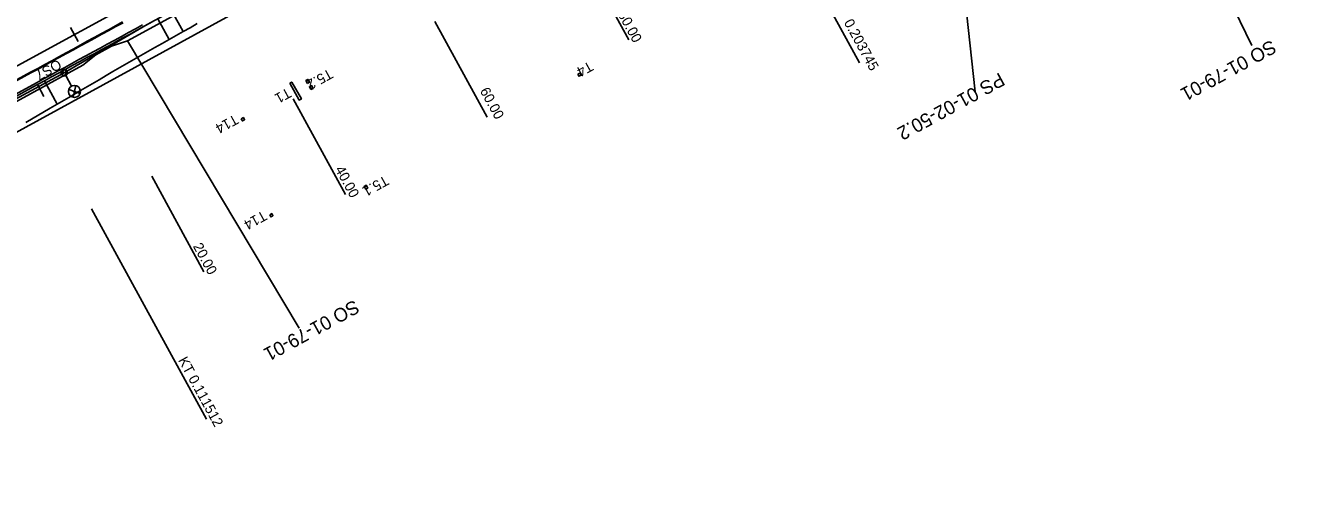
# Model space of a CAD drawing. Extents: x -783978 to -783565, y -1064821 to -1064596.
# Drawn here: x -783865.7 to -783706.3, y -1064790 to -1064732.7 of the extents above; entities that cross this region are included whole.
import ezdxf

# ---------------------------------------------------------------- set-up
doc = ezdxf.new("R2010")
doc.units = 0
for name, color, linetype in [('_PS_SO_číslo', 7, 'Continuous'), ('PS 01_01_10', 7, 'Continuous'), ('PS 01_02_501', 7, 'Continuous'), ('PS 01_02_502', 7, 'Continuous'), ('SO 01_50_01', 7, 'Continuous'), ('SO 01_77_01', 7, 'Continuous'), ('SO 01_79_02', 7, 'Continuous'), ('SO 01_86_02', 7, 'Continuous'), ('SO 01_86_03', 7, 'Continuous')]:
    doc.layers.add(name, color=color, linetype=linetype)

msp = doc.modelspace()

# ---------------------------------------------------------------- linework, layer by layer
at = {"layer": '_PS_SO_číslo'}
for p, q in [((-783752.54, -1064700.01), (-783748.07, -1064740.95)), ((-783725.4, -1064711.21), (-783713.77, -1064735.19)), ((-783853.11, -1064734.61), (-783831.84, -1064770.24))]:
    msp.add_line(p, q, dxfattribs=at)
at = {"layer": 'PS 01_01_10'}
msp.add_lwpolyline([(-783718.94, -1064658.94), (-783725.96, -1064662.69), (-783732.35, -1064665.91), (-783735.21, -1064660.7), (-783789.36, -1064690.35), (-783783.83, -1064700.44), (-783871.44, -1064748.42), (-783875.86, -1064749.83)], dxfattribs=at)
at = {"layer": 'PS 01_02_501'}
msp.add_lwpolyline([(-783952.31, -1064789.97), (-783925.03, -1064771.23), (-783922.86, -1064767.94), (-783921.13, -1064767.23), (-783922.34, -1064769.06), (-783920.82, -1064771.04), (-783917.67, -1064770.42), (-783911.05, -1064766.47), (-783887.43, -1064753.52), (-783871.44, -1064748.42), (-783783.83, -1064700.44), (-783789.36, -1064690.35), (-783735.23, -1064660.71), (-783727.19, -1064659.07), (-783724.3, -1064658.48), (-783715.52, -1064653.99), (-783697.39, -1064644.15), (-783676.27, -1064633.51), (-783655.14, -1064621.89)], dxfattribs=at)
at = {"layer": 'PS 01_02_502'}
msp.add_lwpolyline([(-783952.31, -1064789.97), (-783925.03, -1064771.23), (-783922.86, -1064767.94), (-783921.13, -1064767.23), (-783922.34, -1064769.06), (-783920.82, -1064771.04), (-783917.67, -1064770.42), (-783911.05, -1064766.47), (-783887.43, -1064753.52), (-783871.44, -1064748.42), (-783783.83, -1064700.44), (-783789.36, -1064690.35), (-783735.23, -1064660.71), (-783727.19, -1064659.07), (-783724.3, -1064658.48), (-783715.52, -1064653.99), (-783697.39, -1064644.15), (-783676.27, -1064633.51), (-783655.14, -1064621.89)], dxfattribs=at)
at = {"layer": 'SO 01_50_01'}
for p, q in [((-783867.16, -1064737.91), (-783786.21, -1064693.71)), ((-783776.63, -1064711.26), (-783762.39, -1064737.33)), ((-783797.47, -1064722.64), (-783791, -1064734.49)), ((-783847.62, -1064730.94), (-783846.24, -1064733.48)), ((-783854.61, -1064732.76), (-783853.73, -1064732.28)), ((-783854.61, -1064732.76), (-783853.73, -1064732.28)), ((-783854.56, -1064732.85), (-783853.68, -1064732.37)), ((-783851.13, -1064732.86), (-783850.26, -1064732.38)), ((-783851.13, -1064732.86), (-783850.26, -1064732.38)), ((-783851.13, -1064732.86), (-783850.26, -1064732.38)), ((-783849.38, -1064731.9), (-783847.98, -1064734.46)), ((-783845.37, -1064732.99), (-783844.5, -1064732.49)), ((-783815.02, -1064732.23), (-783808.55, -1064744.07)), ((-783859.23, -1064734.72), (-783860.19, -1064732.96)), ((-783858.12, -1064734.68), (-783857.24, -1064734.2)), ((-783858.12, -1064734.68), (-783857.24, -1064734.2)), ((-783857.24, -1064734.2), (-783856.36, -1064733.72)), ((-783857.24, -1064734.2), (-783856.36, -1064733.72)), ((-783857.19, -1064734.29), (-783856.31, -1064733.81)), ((-783856.36, -1064733.72), (-783855.48, -1064733.24)), ((-783856.36, -1064733.72), (-783855.48, -1064733.24)), ((-783856.31, -1064733.81), (-783855.44, -1064733.33)), ((-783855.48, -1064733.24), (-783854.61, -1064732.76)), ((-783855.48, -1064733.24), (-783854.61, -1064732.76)), ((-783855.44, -1064733.33), (-783854.56, -1064732.85)), ((-783854.77, -1064734.56), (-783853.89, -1064734.08)), ((-783853.89, -1064734.08), (-783853.01, -1064733.6)), ((-783853.77, -1064734.3), (-783852.89, -1064733.82)), ((-783853.77, -1064734.3), (-783852.89, -1064733.82)), ((-783853.77, -1064734.3), (-783852.89, -1064733.82)), ((-783853.01, -1064733.6), (-783852.13, -1064733.12)), ((-783852.89, -1064733.82), (-783852.01, -1064733.34)), ((-783852.89, -1064733.82), (-783852.01, -1064733.34)), ((-783852.89, -1064733.82), (-783852.01, -1064733.34)), ((-783852.13, -1064733.12), (-783851.25, -1064732.64)), ((-783852.01, -1064733.34), (-783851.13, -1064732.86)), ((-783852.01, -1064733.34), (-783851.13, -1064732.86)), ((-783852.01, -1064733.34), (-783851.13, -1064732.86)), ((-783847.98, -1064734.46), (-783847.11, -1064733.97)), ((-783847.11, -1064733.97), (-783846.24, -1064733.48)), ((-783846.24, -1064733.48), (-783845.37, -1064732.99)), ((-783860.75, -1064736.12), (-783859.87, -1064735.64)), ((-783860.75, -1064736.12), (-783859.87, -1064735.64)), ((-783860.7, -1064736.21), (-783859.82, -1064735.73)), ((-783859.87, -1064735.64), (-783858.99, -1064735.16)), ((-783859.87, -1064735.64), (-783858.99, -1064735.16)), ((-783859.82, -1064735.73), (-783858.95, -1064735.25)), ((-783858.99, -1064735.16), (-783858.12, -1064734.68)), ((-783858.99, -1064735.16), (-783858.12, -1064734.68)), ((-783858.95, -1064735.25), (-783858.07, -1064734.77)), ((-783858.07, -1064734.77), (-783857.19, -1064734.29)), ((-783857.4, -1064736), (-783856.52, -1064735.52)), ((-783857.28, -1064736.22), (-783856.4, -1064735.74)), ((-783857.28, -1064736.22), (-783856.4, -1064735.74)), ((-783857.28, -1064736.22), (-783856.4, -1064735.74)), ((-783856.52, -1064735.52), (-783855.64, -1064735.04)), ((-783856.4, -1064735.74), (-783855.52, -1064735.26)), ((-783856.4, -1064735.74), (-783855.52, -1064735.26)), ((-783856.4, -1064735.74), (-783855.52, -1064735.26)), ((-783855.64, -1064735.04), (-783854.77, -1064734.56)), ((-783855.52, -1064735.26), (-783854.65, -1064734.78)), ((-783855.52, -1064735.26), (-783854.65, -1064734.78)), ((-783855.52, -1064735.26), (-783854.65, -1064734.78)), ((-783854.65, -1064734.78), (-783853.77, -1064734.3)), ((-783854.65, -1064734.78), (-783853.77, -1064734.3)), ((-783854.65, -1064734.78), (-783853.77, -1064734.3)), ((-783850.59, -1064735.94), (-783849.72, -1064735.45)), ((-783849.72, -1064735.45), (-783848.85, -1064734.96)), ((-783848.85, -1064734.96), (-783847.98, -1064734.46)), ((-783863.38, -1064737.56), (-783862.51, -1064737.08)), ((-783863.38, -1064737.56), (-783862.51, -1064737.08)), ((-783863.34, -1064737.64), (-783862.46, -1064737.16)), ((-783862.51, -1064737.08), (-783861.63, -1064736.6)), ((-783862.51, -1064737.08), (-783861.63, -1064736.6)), ((-783862.46, -1064737.16), (-783861.58, -1064736.68)), ((-783861.63, -1064736.6), (-783860.75, -1064736.12)), ((-783861.63, -1064736.6), (-783860.75, -1064736.12)), ((-783861.58, -1064736.68), (-783860.7, -1064736.21)), ((-783860.03, -1064737.43), (-783859.15, -1064736.95)), ((-783859.91, -1064737.65), (-783859.03, -1064737.17)), ((-783859.91, -1064737.65), (-783859.03, -1064737.17)), ((-783859.91, -1064737.65), (-783859.03, -1064737.17)), ((-783859.15, -1064736.95), (-783858.28, -1064736.48)), ((-783859.03, -1064737.17), (-783858.16, -1064736.69)), ((-783859.03, -1064737.17), (-783858.16, -1064736.69)), ((-783859.03, -1064737.17), (-783858.16, -1064736.69)), ((-783858.28, -1064736.48), (-783857.4, -1064736)), ((-783858.16, -1064736.69), (-783857.28, -1064736.22)), ((-783858.16, -1064736.69), (-783857.28, -1064736.22)), ((-783858.16, -1064736.69), (-783857.28, -1064736.22)), ((-783854.07, -1064737.92), (-783853.2, -1064737.42)), ((-783853.2, -1064737.42), (-783852.33, -1064736.93)), ((-783852.33, -1064736.93), (-783851.46, -1064736.43)), ((-783851.46, -1064736.43), (-783850.59, -1064735.94)), ((-783868.9, -1064740.57), (-783865.14, -1064738.51)), ((-783868.88, -1064740.67), (-783865.09, -1064738.6)), ((-783866.02, -1064738.99), (-783865.14, -1064738.51)), ((-783865.14, -1064738.51), (-783864.26, -1064738.03)), ((-783865.14, -1064738.51), (-783864.26, -1064738.04)), ((-783865.09, -1064738.6), (-783864.21, -1064738.12)), ((-783864.26, -1064738.04), (-783863.38, -1064737.56)), ((-783864.26, -1064738.03), (-783863.38, -1064737.56)), ((-783864.21, -1064738.12), (-783863.34, -1064737.64)), ((-783863.54, -1064739.35), (-783862.66, -1064738.87)), ((-783862.66, -1064738.87), (-783861.79, -1064738.39)), ((-783862.54, -1064739.09), (-783861.67, -1064738.61)), ((-783862.54, -1064739.09), (-783861.67, -1064738.61)), ((-783862.54, -1064739.09), (-783861.67, -1064738.61)), ((-783861.79, -1064738.39), (-783860.91, -1064737.91)), ((-783861.67, -1064738.61), (-783860.79, -1064738.13)), ((-783861.67, -1064738.61), (-783860.79, -1064738.13)), ((-783861.67, -1064738.61), (-783860.79, -1064738.13)), ((-783860.91, -1064737.91), (-783860.03, -1064737.43)), ((-783860.79, -1064738.13), (-783859.91, -1064737.65)), ((-783860.79, -1064738.13), (-783859.91, -1064737.65)), ((-783860.79, -1064738.13), (-783859.91, -1064737.65)), ((-783856.66, -1064739.44), (-783855.79, -1064738.93)), ((-783855.79, -1064738.93), (-783854.93, -1064738.43)), ((-783854.93, -1064738.43), (-783854.07, -1064737.92)), ((-783869.39, -1064742.55), (-783864.42, -1064739.83)), ((-783869.34, -1064742.8), (-783864.3, -1064740.05)), ((-783869.34, -1064742.8), (-783864.3, -1064740.05)), ((-783865.18, -1064740.53), (-783864.3, -1064740.05)), ((-783864.42, -1064739.83), (-783863.54, -1064739.35)), ((-783864.3, -1064740.05), (-783863.42, -1064739.57)), ((-783864.3, -1064740.05), (-783863.42, -1064739.57)), ((-783864.3, -1064740.05), (-783863.42, -1064739.57)), ((-783864.3, -1064740.05), (-783863.5, -1064741.51)), ((-783863.42, -1064739.57), (-783862.54, -1064739.09)), ((-783863.42, -1064739.57), (-783862.54, -1064739.09)), ((-783863.42, -1064739.57), (-783862.54, -1064739.09)), ((-783863.42, -1064739.57), (-783861.84, -1064742.47)), ((-783859.25, -1064740.95), (-783858.38, -1064740.45)), ((-783858.38, -1064740.45), (-783857.52, -1064739.94)), ((-783857.52, -1064739.94), (-783856.66, -1064739.44)), ((-783861.84, -1064742.47), (-783860.98, -1064741.96)), ((-783860.98, -1064741.96), (-783860.11, -1064741.46)), ((-783860.11, -1064741.46), (-783859.25, -1064740.95)), ((-783832.58, -1064741.81), (-783826.11, -1064753.66)), ((-783865.74, -1064744.75), (-783862.7, -1064742.97)), ((-783862.7, -1064742.97), (-783861.84, -1064742.47)), ((-783850.13, -1064751.4), (-783843.66, -1064763.24)), ((-783857.58, -1064755.46), (-783843.34, -1064781.53))]:
    msp.add_line(p, q, dxfattribs=at)
at = {"layer": 'SO 01_77_01'}
for points in [[(-783797.32, -1064738.76), (-783797.06, -1064738.61), (-783796.91, -1064738.88), (-783797.17, -1064739.02)], [(-783830.82, -1064739.9), (-783830.56, -1064739.75), (-783830.76, -1064739.4), (-783831.02, -1064739.55)], [(-783830.39, -1064740.67), (-783830.13, -1064740.52), (-783830.32, -1064740.17), (-783830.59, -1064740.32)], [(-783839.03, -1064744.29), (-783838.77, -1064744.14), (-783838.62, -1064744.41), (-783838.89, -1064744.55)], [(-783823.6, -1064753.01), (-783823.34, -1064752.87), (-783823.54, -1064752.52), (-783823.8, -1064752.67)], [(-783835.5, -1064756.19), (-783835.24, -1064756.04), (-783835.1, -1064756.31), (-783835.36, -1064756.45)]]:
    msp.add_lwpolyline(points, close=True, dxfattribs=at)
msp.add_lwpolyline([(-783833.02, -1064739.88), (-783831.85, -1064741.97), (-783831.58, -1064741.83), (-783832.76, -1064739.73), (-783833.02, -1064739.88)], dxfattribs=at)
at = {"layer": 'SO 01_79_02'}
msp.add_lwpolyline([(-783745.08, -1064674.98), (-783746.51, -1064675.76), (-783748.15, -1064676.66), (-783749.69, -1064678.14), (-783784.26, -1064697.01), (-783798.19, -1064704.62), (-783800.06, -1064705.37), (-783802.52, -1064706.72), (-783803.71, -1064707.63), (-783853.11, -1064734.61), (-783855.1, -1064735.3), (-783857.05, -1064736.37), (-783858.65, -1064737.64), (-783871.68, -1064744.75), (-783877.06, -1064744.61), (-783887.43, -1064744.06), (-783898.09, -1064743.49), (-783899.42, -1064743.42)], dxfattribs=at)
at = {"layer": 'SO 01_86_02'}
for p, q in [((-783861.05, -1064738.18), (-783861.25, -1064738.86)), ((-783860.67, -1064738.31), (-783860.86, -1064738.95)), ((-783860.06, -1064740.24), (-783860.78, -1064738.92)), ((-783859.53, -1064740.16), (-783859.88, -1064741.62)), ((-783859, -1064741.14), (-783860.41, -1064740.65))]:
    msp.add_line(p, q, dxfattribs=at)
msp.add_lwpolyline([(-783878.19, -1064744.28), (-783875.13, -1064744.35), (-783874.69, -1064744.33), (-783873.25, -1064744.16), (-783872.31, -1064743.98), (-783871.22, -1064743.7), (-783870.51, -1064743.49), (-783869.8, -1064743.21), (-783869.18, -1064742.97), (-783868.71, -1064742.77), (-783868.39, -1064742.61), (-783868.08, -1064742.45), (-783860.97, -1064738.57), (-783850.67, -1064732.61), (-783846.25, -1064730.19), (-783839.95, -1064727.09), (-783822.43, -1064717.43), (-783813.36, -1064712.52), (-783804.29, -1064707.61), (-783794.47, -1064702.25), (-783784.66, -1064696.9), (-783775.73, -1064692.01), (-783766.81, -1064687.13), (-783750.63, -1064678.28)], dxfattribs=at)
msp.add_lwpolyline([(-783861.09, -1064738.98), (-783860.57, -1064738.68), (-783860.86, -1064738.16), (-783861.38, -1064738.46)], close=True, dxfattribs=at)
for centre, radius in [((-783860.97, -1064738.57), 0.4), ((-783859.71, -1064740.89), 0.749)]:
    msp.add_circle(centre, radius, dxfattribs=at)
at = {"layer": 'SO 01_86_03'}
msp.add_lwpolyline([(-783722.52, -1064661.79), (-783724.82, -1064663.05), (-783735.21, -1064660.7), (-783787.33, -1064689.24), (-783786.82, -1064690.18), (-783783.36, -1064696.8), (-783781.94, -1064699.41), (-783783.83, -1064700.44), (-783871.44, -1064748.42), (-783875.86, -1064749.83), (-783877.54, -1064747.39), (-783875.86, -1064749.83), (-783887.43, -1064753.52), (-783911.05, -1064766.47), (-783917.67, -1064770.42), (-783920.82, -1064771.04), (-783922.34, -1064769.06), (-783922.5, -1064767.05)], dxfattribs=at)

# ---------------------------------------------------------------- texts
at = {"layer": '_PS_SO_číslo'}
for s, rotation, p in [('SO 01-79-01', 208.6832, (-783711.35, -1064734.44)), ('PS 01-02-50.2', 208.6831, (-783745.02, -1064738.5)), ('SO 01-79-01', 208.7111, (-783825, -1064766.67))]:
    msp.add_text(s, height=1.7, rotation=rotation, dxfattribs=at).set_placement(p)
at = {"layer": 'SO 01_50_01'}
for s, p in [('KÚ 0.203745', (-783765.71, -1064729.89)), ('80.00', (-783792.4, -1064731.3)), ('60.00', (-783809.49, -1064740.81)), ('40.00', (-783827.44, -1064750.54)), ('20.00', (-783845.05, -1064760.08)), ('KT 0.111512', (-783846.88, -1064774.21))]:
    msp.add_text(s, height=1.25, rotation=298.6368, dxfattribs=at).set_placement(p)
at = {"layer": 'SO 01_77_01'}
for s, p in [('T4', (-783795.87, -1064737.1)), ('T5.2', (-783828.13, -1064738.04)), ('T1', (-783833.29, -1064740.4)), ('T14', (-783839.84, -1064743.7)), ('T5.1', (-783821.21, -1064751.27)), ('T14', (-783836.32, -1064755.63))]:
    msp.add_text(s, height=1.25, rotation=208.9107, dxfattribs=at).set_placement(p)
at = {"layer": 'SO 01_86_02'}
msp.add_text('OS7', height=1.25, rotation=209.446, dxfattribs=at).set_placement((-783861.77, -1064736.85))

doc.saveas('drawing.dxf')
